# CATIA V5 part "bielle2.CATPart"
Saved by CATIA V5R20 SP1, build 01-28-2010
Part number: bielle2
Bounding box of the stored display mesh (mm): x 200 to 530, y -62.489 to 62.489, z -782.455 to 49.955
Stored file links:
  C:\Users\Nicolas\Documents\Ifma\2A\S3\iao\projet\bielle2.CATPart
  C:\Users\Nicolas\Documents\Ifma\2A\S3\iao\projet\Product1.CATProduct
  C:\Users\Nicolas\Documents\Ifma\2A\S3\iao\projet\triangle.CATPart
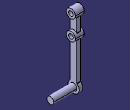
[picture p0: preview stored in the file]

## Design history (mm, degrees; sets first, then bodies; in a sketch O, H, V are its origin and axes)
Set1
  Plane1: linked copy from another document
  Point1: linked copy from another document
  Line1: linked copy from another document
  Plane2: linked copy from another document
  Plane3: linked copy from another document
  Point2: linked copy from another document
Body1 (main body)
  Sketch1 on Plane1, origin (250, 0, 0), H (0, 1, 0), V (0, 0, 1)
    arc A1 centre (0, 0) radius 50 from (37.5, -33.0719) to (-37.5, -33.0719) ccw
    point P1 (0, 0)
    arc A2 centre (0, -720) radius 62.5 from (-37.5, -670) to (37.5, -670) ccw
    point P2 (0, -720)
    arc A3 centre (0, -220) radius 50 from (37.5, -253.0719) to (37.5, -186.9281) ccw
    point P3 (0, -220)
    reference projected point E1 (0, -220) from Point1
    reference projected point E2 (0, -720) from Line1
    line L1 (37.5, -33.0719) -> (37.5, -186.9281)
    line L2 (-37.5, -670) -> (-37.5, -253.0719)
    point P9 (37.5, -253.0719)
    arc A4 centre (0, -220) radius 50 from (-37.5, -186.9281) to (-37.5, -253.0719) ccw
    point P11 (-37.5, -186.9281)
    line L3 (-37.5, -186.9281) -> (-37.5, -33.0719)
    line L4 (37.5, -253.0719) -> (37.5, -670)
    radius A3 = 50
    radius A1 = 50
    radius A2 = 62.5
    distance L1 L2 = 75
    coincidence: P1 O, P3 E1, P2 E2, L1 P9, L2 P11, A3 A4, L2 L3, L1 L4
    vertical: L1 V, L2 V, L3 V, L4 V
    symmetry: L4 L2 V
  Pad1: profile Sketch1, direction (1, 0, 0), length 20, mirrored extent
  Sketch2 on Plane1, origin (250, 0, 0), H (0, 1, 0), V (0, 0, 1)
    circle A1 centre (0, 0) radius 50
    circle A2 centre (0, -220) radius 50
    reference projected arc E1 centre (0, 0) radius 50 from (37.5, -33.0719) to (-37.5, -33.0719) ccw from edge [face of Pad1 from Sketch1.A1 | end face of Pad1]
    reference projected arc E2 centre (0, -220) radius 50 from (37.5, -253.0719) to (37.5, -186.9281) ccw from edge [face of Pad1 from Sketch1.A3 | end face of Pad1]
    coincidence: A1 E1, A2 E2
  Pad2: profile Sketch2, direction (1, 0, 0), up to Plane2, opposite side up to Plane3
  Sketch3 on Plane1, origin (250, 0, 0), H (0, 1, 0), V (0, 0, 1)
    circle A1 centre (0, -720) radius 37.5
    point P1 (0, -720)
    reference projected arc E1 centre (0, -720) radius 62.5 from (-37.5, -670) to (37.5, -670) ccw from edge [face of Pad1 from Sketch1.A2 | end face of Pad1]
    radius A1 = 37.5
    coincidence: P1 V
    concentricity: A1 E1
  Pad3: profile Sketch3, direction (1, 0, 0), length 280
  Sketch4 on start face of Pad2, origin (300, 0, -300), H (0, 1, 0), V (0, 0, 1)
    point P1 (0, 80)
    reference projected point E1 (0, 80) from Point1
    coincidence: E1 P1
  Hole1: placed by Sketch4, at (300, 0, -220) direction (-1, 0, 0), diameter 50, through (limit type 3)
  Sketch5 on start face of Pad2, origin (300, 0, 0), H (0, 1, 0), V (0, 0, 1)
    point P1 (0, 0)
    reference projected point E1 (0, 0) from Point2
    coincidence: E1 P1
  Hole2: placed by Sketch5, at (300, 0, 0) direction (-1, 0, 0), diameter 50, through (limit type 3)
  Fillet1: radius 5, on edge [face of Pad1 from Sketch1.L1 | face of Pad1]; edge [face of Pad1 | face of Pad1 from Sketch1.L3]; edge [face of Pad1 from Sketch1.L3 | face of Pad2 from Sketch2.A1]; edge [face of Pad2 from Sketch2.A1 | face of Pad1 from Sketch1.L1]; edge [face of Pad1 from Sketch1.L4 | face of Pad1 from Sketch1.A2]; edge [face of Pad1 from Sketch1.L2 | face of Pad3]; edge [face of Pad2 | face of Pad1 from Sketch1.L4]; edge [face of Pad1 from Sketch1.L2 | face of Pad2]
